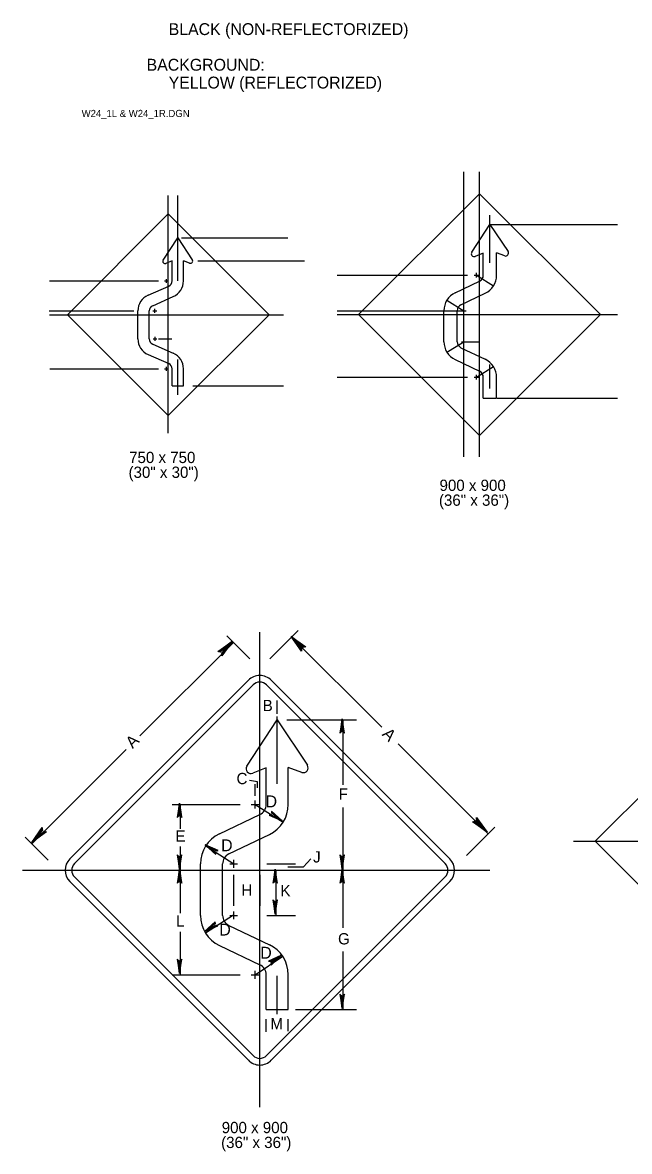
# Model space of a CAD drawing. Extents: x 0 to 0.249, y -0.213 to 0.259.
# Drawn here: x 0.0001 to 0.1279, y -0.2135 to 0.0243 of the extents above; entities that cross this region are included whole.
import ezdxf

# ---------------------------------------------------------------- set-up
doc = ezdxf.new("R2010")
doc.units = 0
doc.layers.add('1', color=7, linetype='Continuous')
doc.layers.add('3', color=7, linetype='Continuous')

# ---------------------------------------------------------------- blocks, each defined once
blk = doc.blocks.new('RARROW')
at = {"layer": '3'}
for p, q in [((-2.156, 0.28500000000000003), (-2.2665, 0.384625)), ((-2.2665, 0.384625), (0, 0)), ((0, 0), (-2.2665, -0.379125)), ((-2.156, 0.28500000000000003), (-2.075625, 0.12075)), ((0, 0), (-2.156, 0.28500000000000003)), ((-2.14975, -0.2705), (0, 0)), ((-2.075625, 0.12075), (0, 0)), ((0, 0), (-2.074, -0.108)), ((-2.2665, -0.379125), (-2.14975, -0.2705)), ((-2.074, -0.108), (-2.14975, -0.2705))]:
    blk.add_line(p, q, dxfattribs=at)

msp = doc.modelspace()

# ---------------------------------------------------------------- linework, layer by layer
at = {"layer": '1'}
for p, q in [((0.09465737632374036, -0.02410788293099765), (0.0984895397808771, -0.018239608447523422)), ((0.0984895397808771, -0.018239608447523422), (0.1253779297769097, -0.018239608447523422)), ((0.0984895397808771, -0.018239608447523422), (0.10229869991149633, -0.023980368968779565)), ((0.029677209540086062, -0.02575401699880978), (0.03274550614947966, -0.02105546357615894)), ((0.03274550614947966, -0.02105546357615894), (0.03580954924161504, -0.025673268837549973)), ((0.03354259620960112, -0.02104652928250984), (0.05594957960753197, -0.02104652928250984)), ((0.03154550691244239, -0.02592546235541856), (0.030263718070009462, -0.026459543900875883)), ((0.03154550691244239, -0.030158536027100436), (0.03154550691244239, -0.02592546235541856)), ((0.03394550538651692, -0.030158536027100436), (0.03394550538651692, -0.02592546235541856)), ((0.03524814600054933, -0.02639069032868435), (0.03394550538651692, -0.02592546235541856)), ((0.03699486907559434, -0.02591499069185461), (0.059401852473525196, -0.02591499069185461)), ((0.09708954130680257, -0.024281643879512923), (0.09539071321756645, -0.024989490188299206)), ((0.09708954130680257, -0.028938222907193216), (0.09708954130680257, -0.024281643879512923)), ((0.09988953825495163, -0.028938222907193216), (0.09988953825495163, -0.024264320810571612)), ((0.10159433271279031, -0.02487317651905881), (0.09988953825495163, -0.024264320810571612)), ((0.09568641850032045, -0.02943960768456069), (0.09568641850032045, -0.028439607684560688)), ((0.005764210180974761, -0.030154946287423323), (0.028662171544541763, -0.030154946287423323)), ((0.029926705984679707, -0.030160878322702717), (0.03076003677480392, -0.030160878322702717)), ((0.030343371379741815, -0.03057754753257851), (0.030343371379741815, -0.029744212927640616)), ((0.06631197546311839, -0.02893960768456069), (0.09378954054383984, -0.02893960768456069)), ((0.09117587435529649, -0.032651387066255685), (0.09629409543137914, -0.03020096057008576)), ((0.09518641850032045, -0.02893960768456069), (0.09618641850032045, -0.02893960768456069)), ((0.09568641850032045, -0.02893960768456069), (0.09924322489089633, -0.031176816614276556)), ((0.02649533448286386, -0.033161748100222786), (0.030828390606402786, -0.031257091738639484)), ((0.09238498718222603, -0.03517686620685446), (0.09750320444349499, -0.032726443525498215)), ((0.027461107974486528, -0.0353588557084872), (0.03179416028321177, -0.0334541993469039)), ((0.08943585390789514, -0.03420101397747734), (0.0929895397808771, -0.036439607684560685)), ((0.0056722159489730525, -0.036453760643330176), (0.02349550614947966, -0.036453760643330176)), ((0.024343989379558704, -0.04235453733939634), (0.024343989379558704, -0.036457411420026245)), ((0.026743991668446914, -0.04235453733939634), (0.026743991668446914, -0.036457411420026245)), ((0.02752732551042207, -0.036457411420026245), (0.028360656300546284, -0.036457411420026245)), ((0.02794399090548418, -0.03687407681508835), (0.02794399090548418, -0.03604074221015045)), ((0.06631197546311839, -0.036439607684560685), (0.0929895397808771, -0.036439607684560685)), ((0.08878954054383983, -0.04294057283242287), (0.08878954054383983, -0.036439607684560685)), ((0.09158954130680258, -0.04294058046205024), (0.09158954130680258, -0.036439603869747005)), ((0.0924895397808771, -0.036439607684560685), (0.0934895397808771, -0.036439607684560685)), ((0.0929895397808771, -0.036939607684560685), (0.0929895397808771, -0.035939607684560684)), ((0.027532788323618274, -0.04235338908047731), (0.028366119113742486, -0.04235338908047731)), ((0.02794945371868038, -0.0427700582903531), (0.02794945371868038, -0.041936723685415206)), ((0.02871919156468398, -0.04236008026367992), (0.03146919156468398, -0.04236008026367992)), ((0.0929895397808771, -0.043439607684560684), (0.0929895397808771, -0.04243960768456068)), ((0.02746021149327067, -0.043452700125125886), (0.03179684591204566, -0.045363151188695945)), ((0.0894362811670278, -0.045179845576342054), (0.0929895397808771, -0.042939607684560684)), ((0.09238546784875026, -0.044203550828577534), (0.09750175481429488, -0.04665064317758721)), ((0.0924895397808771, -0.042939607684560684), (0.0934895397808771, -0.042939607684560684)), ((0.0929895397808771, -0.042939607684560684), (0.09628954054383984, -0.042939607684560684)), ((0.026492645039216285, -0.0456490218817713), (0.030829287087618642, -0.04755947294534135)), ((0.0911773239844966, -0.04672948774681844), (0.09629361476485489, -0.0491765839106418)), ((0.0057697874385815, -0.04865509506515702), (0.028667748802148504, -0.04865509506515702)), ((0.029929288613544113, -0.0486578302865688), (0.03076262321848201, -0.0486578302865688)), ((0.030345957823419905, -0.04907449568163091), (0.030345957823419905, -0.0482411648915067)), ((0.03154550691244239, -0.05225546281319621), (0.03154550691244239, -0.048657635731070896)), ((0.03394550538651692, -0.05225546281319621), (0.03394550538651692, -0.04865763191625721)), ((0.0956896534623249, -0.05043960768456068), (0.09924279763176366, -0.0482002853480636)), ((0.03154550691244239, -0.05225546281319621), (0.03394550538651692, -0.05225546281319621)), ((0.03588224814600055, -0.05225546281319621), (0.05498582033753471, -0.05225546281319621)), ((0.06631197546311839, -0.05043960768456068), (0.09378954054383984, -0.05043960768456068)), ((0.0951896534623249, -0.05043960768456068), (0.0961896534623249, -0.05043960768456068)), ((0.0956896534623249, -0.050939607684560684), (0.0956896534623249, -0.04993960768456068)), ((0.09708954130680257, -0.054839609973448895), (0.09708954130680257, -0.050439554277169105)), ((0.09988953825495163, -0.054839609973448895), (0.09988953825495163, -0.05043955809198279)), ((0.09708954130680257, -0.054839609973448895), (0.09988953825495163, -0.054839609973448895)), ((0.0999895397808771, -0.054839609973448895), (0.1253779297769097, -0.054839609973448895)), ((0.047300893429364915, -0.13236573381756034), (0.05368782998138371, -0.12258527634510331)), ((0.05368782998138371, -0.12258527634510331), (0.06003643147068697, -0.13215321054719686)), ((0.05135450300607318, -0.13265533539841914), (0.048523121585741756, -0.13383507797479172)), ((0.05135450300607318, -0.1404162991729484), (0.05135450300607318, -0.13265533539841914)), ((0.05602116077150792, -0.1404162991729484), (0.05602116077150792, -0.13262646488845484)), ((0.05886248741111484, -0.13364122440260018), (0.05602116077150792, -0.13262646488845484)), ((0.04901596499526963, -0.14125194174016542), (0.04901596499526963, -0.1395852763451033)), ((0.04149839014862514, -0.14660490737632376), (0.050028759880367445, -0.14252086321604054)), ((0.048182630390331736, -0.14041860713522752), (0.04984929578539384, -0.14041860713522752)), ((0.043513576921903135, -0.15081403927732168), (0.05204393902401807, -0.14673000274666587)), ((0.044521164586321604, -0.15375194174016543), (0.044521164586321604, -0.1520852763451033)), ((0.03752116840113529, -0.16375355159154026), (0.03752116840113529, -0.1529186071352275)), ((0.042187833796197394, -0.16375356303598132), (0.042187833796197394, -0.15291860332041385)), ((0.043687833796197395, -0.1529186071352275), (0.0453544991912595, -0.1529186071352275)), ((0.043687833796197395, -0.1637519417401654), (0.0453544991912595, -0.1637519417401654)), ((0.044521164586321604, -0.1645852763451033), (0.044521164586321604, -0.16291860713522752)), ((0.043514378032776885, -0.1658585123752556), (0.05204152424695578, -0.16993700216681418)), ((0.04150080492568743, -0.17006840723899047), (0.0500279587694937, -0.17414690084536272)), ((0.04902135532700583, -0.1770852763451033), (0.04902135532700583, -0.17541860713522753)), ((0.04818802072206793, -0.17625194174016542), (0.049854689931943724, -0.17625194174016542)), ((0.05135450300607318, -0.18358528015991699), (0.05135450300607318, -0.17625185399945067)), ((0.05602116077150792, -0.18358528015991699), (0.05602116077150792, -0.17625185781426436)), ((0.05135450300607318, -0.18358528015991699), (0.05602116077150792, -0.18358528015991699))]:
    msp.add_line(p, q, dxfattribs=at)
for centre, radius, start, end in [((0.09515994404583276, -0.02443564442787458), 0.0005999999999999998, 146.8886580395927, 292.619864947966), ((0.10179613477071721, -0.02430813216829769), 0.0006, 250.34617594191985, 33.111341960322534), ((0.030345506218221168, -0.030158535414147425), 0.0012, 293.7285668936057, 0), ((0.0303455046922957, -0.03015853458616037), 0.0036000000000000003, 293.7285832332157, 5.684341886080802e-14), ((0.09568954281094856, -0.028938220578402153), 0.0014, 295.58345846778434, 0), ((0.09568953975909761, -0.028938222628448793), 0.004200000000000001, 295.5834507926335, 0), ((0.02794398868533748, -0.036457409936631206), 0.0036000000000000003, 113.72857081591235, 180), ((0.09298954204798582, -0.03643960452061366), 0.004200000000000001, 115.58345385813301, 180), ((0.02794399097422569, -0.03645740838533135), 0.0012, 113.7285780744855, 180), ((0.09298954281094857, -0.03643960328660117), 0.0014, 115.58343656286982, 180), ((0.02794398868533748, -0.04235453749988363), 0.0036000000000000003, 180, 246.22470832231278), ((0.02794399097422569, -0.04235453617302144), 0.0012, 180.00000000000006, 246.22471231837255), ((0.09298954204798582, -0.042940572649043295), 0.004200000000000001, 180.00000000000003, 244.43845176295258), ((0.09298954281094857, -0.04294057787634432), 0.0014, 180, 244.43846100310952), ((0.0303455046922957, -0.048657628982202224), 0.0036000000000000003, 0, 66.22472411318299), ((0.09568953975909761, -0.05043955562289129), 0.004200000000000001, 0, 64.4384641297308), ((0.030345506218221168, -0.048657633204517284), 0.0012, 1.4210854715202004e-14, 66.22469809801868), ((0.09568954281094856, -0.05043955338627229), 0.0014, 0, 64.43844982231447), ((0.04813850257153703, -0.13291200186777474), 0.0009999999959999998, 146.8886580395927, 292.619864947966), ((0.05919882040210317, -0.13269948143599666), 0.0009999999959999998, 250.34617594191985, 33.111341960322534), ((0.04902116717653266, -0.14041629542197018), 0.002333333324, 295.58345846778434, 0), ((0.04902116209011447, -0.14041629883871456), 0.006999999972, 295.5834507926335, 0), ((0.04452116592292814, -0.15291860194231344), 0.006999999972, 115.58345385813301, 180), ((0.044521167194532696, -0.15291859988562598), 0.002333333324, 115.58343656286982, 180), ((0.04452116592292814, -0.16375354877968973), 0.006999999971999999, 180.00000000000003, 244.43845176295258), ((0.044521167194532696, -0.16375355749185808), 0.0023333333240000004, 180, 244.43846100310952), ((0.04902116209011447, -0.17625185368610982), 0.006999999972, 0, 64.4384641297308), ((0.04902116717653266, -0.17625184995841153), 0.002333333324, 0, 64.43844982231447)]:
    msp.add_arc(centre, radius, start, end, dxfattribs=at)
at = {"layer": '3'}
for p, q in [((0.0929895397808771, -0.06719206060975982), (0.0929895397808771, -0.0071400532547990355)), ((0.09628954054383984, -0.06719206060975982), (0.09628954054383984, -0.0071400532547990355)), ((0.07083369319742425, -0.03723960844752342), (0.09628954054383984, -0.011783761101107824)), ((0.12174538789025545, -0.03723960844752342), (0.09628954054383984, -0.011783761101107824)), ((0.03074550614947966, -0.062215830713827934), (0.03074550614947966, -0.01217250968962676)), ((0.03274550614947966, -0.03015546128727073), (0.03274550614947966, -0.01217250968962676)), ((0.009532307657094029, -0.0372554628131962), (0.03074550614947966, -0.01604226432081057)), ((0.05195870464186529, -0.0372554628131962), (0.03074550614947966, -0.01604226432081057)), ((0.0984895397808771, -0.026316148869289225), (0.0984895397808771, -0.016316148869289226)), ((0.005764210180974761, -0.0372554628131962), (0.05498582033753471, -0.0372554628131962)), ((0.03074550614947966, -0.058468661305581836), (0.009532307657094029, -0.0372554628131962)), ((0.03074550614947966, -0.058468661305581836), (0.05195870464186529, -0.0372554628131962)), ((0.06631197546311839, -0.03723960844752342), (0.1253779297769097, -0.03723960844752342)), ((0.09628954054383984, -0.06269545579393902), (0.07083369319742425, -0.03723960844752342)), ((0.09628954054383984, -0.06269545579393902), (0.12174538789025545, -0.03723960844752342)), ((0.03274550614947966, -0.05416013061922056), (0.03274550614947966, -0.04667992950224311)), ((0.0984895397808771, -0.052836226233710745), (0.0984895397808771, -0.0477796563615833)), ((0.05002116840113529, -0.2041726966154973), (0.05002116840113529, -0.1040860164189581)), ((0.052142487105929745, -0.10970421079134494), (0.0581169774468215, -0.1037297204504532)), ((0.024759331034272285, -0.12597806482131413), (0.04446651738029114, -0.10627087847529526)), ((0.047899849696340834, -0.10970421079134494), (0.04305230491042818, -0.1048566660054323)), ((0.07570204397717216, -0.12414321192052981), (0.05670276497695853, -0.10514393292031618)), ((0.009998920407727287, -0.15184777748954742), (0.04761700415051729, -0.11422969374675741)), ((0.010988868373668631, -0.15283772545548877), (0.04860695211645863, -0.11521964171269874)), ((0.05143538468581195, -0.11521964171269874), (0.08905346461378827, -0.15283772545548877)), ((0.05242533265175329, -0.11422969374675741), (0.0900434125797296, -0.15184777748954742)), ((0.05368782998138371, -0.12131447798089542), (0.05368782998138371, -0.11852706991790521)), ((0.05368782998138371, -0.13604617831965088), (0.05368782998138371, -0.12187789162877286)), ((0.05568782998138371, -0.12258527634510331), (0.07040427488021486, -0.12258527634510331)), ((0.06760427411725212, -0.13627281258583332), (0.06760427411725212, -0.12258527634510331)), ((0.12062693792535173, -0.1481597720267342), (0.14608278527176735, -0.12270392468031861)), ((0.09813922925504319, -0.14658039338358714), (0.07918378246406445, -0.12762494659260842)), ((0.002040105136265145, -0.14869729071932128), (0.021883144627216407, -0.12885425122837)), ((0.04901596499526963, -0.1385852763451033), (0.04901596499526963, -0.1361297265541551)), ((0.050021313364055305, -0.1385852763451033), (0.050021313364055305, -0.1361297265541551)), ((0.031574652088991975, -0.14041860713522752), (0.0458544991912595, -0.14041860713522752)), ((0.033337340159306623, -0.14552281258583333), (0.033337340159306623, -0.14041860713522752)), ((0.04901596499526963, -0.14041860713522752), (0.05494397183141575, -0.14414728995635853)), ((0.06760427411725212, -0.15425194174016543), (0.06760427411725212, -0.1410127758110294)), ((0.005473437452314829, -0.15213062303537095), (0.0006258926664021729, -0.1472830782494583)), ((0.09357895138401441, -0.15114067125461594), (0.09955344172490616, -0.14516618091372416)), ((0.033337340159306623, -0.15425194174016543), (0.033337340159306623, -0.14927281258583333)), ((0.03864696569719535, -0.14911153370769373), (0.044521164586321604, -0.1529186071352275)), ((0.11610522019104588, -0.1481597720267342), (0.17517117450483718, -0.1481597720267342)), ((0.14608278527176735, -0.17361561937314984), (0.12062693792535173, -0.1481597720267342)), ((5.855739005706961e-05, -0.15425194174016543), (0.09850181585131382, -0.15425194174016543)), ((0.033337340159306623, -0.16327281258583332), (0.033337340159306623, -0.15425194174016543)), ((0.05152116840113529, -0.1529186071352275), (0.057521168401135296, -0.1529186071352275)), ((0.05152116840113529, -0.15424646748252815), (0.057521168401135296, -0.15424646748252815)), ((0.05345628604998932, -0.1637519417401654), (0.05345628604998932, -0.15425194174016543)), ((0.06760427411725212, -0.16639781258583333), (0.06760427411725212, -0.15425194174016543)), ((0.04761700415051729, -0.19427418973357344), (0.009998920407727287, -0.15665610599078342)), ((0.04860695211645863, -0.19328424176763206), (0.010988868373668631, -0.15566615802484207)), ((0.044521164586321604, -0.1617519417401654), (0.044521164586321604, -0.15525194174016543)), ((0.050083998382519, -0.1617519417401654), (0.050083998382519, -0.15525194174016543)), ((0.08905346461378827, -0.15566615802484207), (0.05143538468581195, -0.19328424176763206)), ((0.0900434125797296, -0.15665610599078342), (0.05242533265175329, -0.19427418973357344)), ((0.03855387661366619, -0.16741298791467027), (0.044500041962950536, -0.1636640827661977)), ((0.05152116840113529, -0.1637519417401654), (0.057521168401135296, -0.1637519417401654)), ((0.033337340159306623, -0.17625194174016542), (0.033337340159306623, -0.16719480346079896)), ((0.04902135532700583, -0.17625194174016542), (0.05485345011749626, -0.1723808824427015)), ((0.06760427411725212, -0.18358528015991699), (0.06760427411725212, -0.17132847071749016)), ((0.031574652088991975, -0.17625194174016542), (0.0458544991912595, -0.17625194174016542)), ((0.05368782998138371, -0.18457451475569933), (0.05368782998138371, -0.1765176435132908)), ((0.05752116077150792, -0.18358528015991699), (0.07040427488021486, -0.18358528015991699)), ((0.05135450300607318, -0.18827281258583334), (0.05135450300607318, -0.185585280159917)), ((0.05602116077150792, -0.18814781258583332), (0.05602116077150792, -0.185585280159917))]:
    msp.add_line(p, q, dxfattribs=at)
for points in [[(0.04950954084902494, -0.13690055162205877), (0.04950954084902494, -0.1355994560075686), (0.04782760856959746, -0.1353299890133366)], [(0.05592821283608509, -0.15354288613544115), (0.059258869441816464, -0.15354288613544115), (0.06078917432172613, -0.1518324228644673)]]:
    msp.add_lwpolyline(points, dxfattribs=at)
for centre, radius, start, end in [((0.030079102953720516, -0.026016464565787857), 0.00048, 146.85424022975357, 292.6199636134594), ((0.03540958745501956, -0.02593865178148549), 0.00048, 250.34624416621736, 33.565410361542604), ((0.0500211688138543, -0.11663385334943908), 0.0034, 44.99999742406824, 135), ((0.0500211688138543, -0.11663385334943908), 0.002, 44.99999742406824, 135), ((0.012403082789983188, -0.15425193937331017), 0.0034, 135.00000000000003, 225.00000000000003), ((0.08763925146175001, -0.15425193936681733), 0.0034, 315.0000025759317, 44.99999726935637), ((0.012403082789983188, -0.15425193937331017), 0.002, 135.00000000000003, 225.00000000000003), ((0.08763925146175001, -0.15425193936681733), 0.002, 315.0000025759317, 44.99999726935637), ((0.05002116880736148, -0.19187002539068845), 0.0034, 225, 315.00000273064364), ((0.05002116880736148, -0.19187002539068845), 0.002, 225, 315.00000273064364)]:
    msp.add_arc(centre, radius, start, end, dxfattribs=at)

# ---------------------------------------------------------------- block references
for p, xscale, yscale, rotation in [((0.056625, -0.105), 0.0016545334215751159, 0.0016366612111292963, 135.00000000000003), ((0.04425, -0.106), 0.0016545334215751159, 0.0016366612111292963, 44.999999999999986), ((0.067375, -0.122375), 0.0013236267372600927, -0.001309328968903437, 90), ((0.033125, -0.140125), 0.0013236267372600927, -0.001309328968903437, 90), ((0.05475, -0.143875), 0.0013236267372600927, -0.0013093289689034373, -32.937747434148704), ((0.097875, -0.14625), 0.0016545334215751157, 0.001636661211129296, -45), ((0.002, -0.148375), 0.001654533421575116, 0.001636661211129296, -135), ((0.0385, -0.148875), 0.0013236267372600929, -0.001309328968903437, 146.65790015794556), ((0.033125, -0.154), 0.0013236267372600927, -0.001309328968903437, -90), ((0.067375, -0.154), 0.0013236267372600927, -0.001309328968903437, -90), ((0.033125, -0.154), 0.0013236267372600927, -0.001309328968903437, 90), ((0.05325, -0.154), 0.0013236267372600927, -0.001309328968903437, 90), ((0.067375, -0.154), 0.0013236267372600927, -0.001309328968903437, 90), ((0.05325, -0.1635), 0.0013236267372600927, -0.001309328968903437, -90), ((0.038375, -0.167125), 0.0013236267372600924, -0.001309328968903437, -147.979386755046), ((0.033125, -0.176), 0.0013236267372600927, -0.001309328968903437, -90), ((0.054625, -0.172125), 0.0013236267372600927, -0.0013093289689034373, 33.673578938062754), ((0.067375, -0.183375), 0.0013236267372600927, -0.001309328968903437, -90)]:
    msp.add_blockref('RARROW', p, dxfattribs=dict(at, xscale=xscale, yscale=yscale, rotation=rotation))

# ---------------------------------------------------------------- texts
at = {"layer": '1'}
for s, height, p in [('      BLACK (NON-REFLECTORIZED)', 0.0024997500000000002, (0.02525, 0.021625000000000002)), (' BACKGROUND:', 0.0024997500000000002, (0.02525, 0.014125)), ('      YELLOW (REFLECTORIZED)', 0.0024997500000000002, (0.02525, 0.010375)), ('W24_1L & W24_1R.DGN', 0.0015, (0.0125, 0.004375))]:
    msp.add_text(s, height=height, dxfattribs=at).set_placement(p)
at = {"layer": '3'}
for s, height, p in [('750 x 750', 0.0023752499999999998, (0.0225, -0.0685)), ('(30" x 30")', 0.0023752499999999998, (0.022375, -0.07162500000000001)), ('900 x 900', 0.0023752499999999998, (0.08787500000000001, -0.074375)), ('(36" x 36")', 0.0023752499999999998, (0.08775000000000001, -0.0775)), ('B', 0.0023752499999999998, (0.050625, -0.12075)), ('C', 0.0023752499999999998, (0.045125, -0.136125)), ('F', 0.0023752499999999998, (0.066625, -0.139375)), ('D', 0.0024997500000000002, (0.051250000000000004, -0.14100000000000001)), ('E', 0.0023752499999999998, (0.03225, -0.14825)), ('D', 0.0024997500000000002, (0.041875, -0.15025)), ('J', 0.0023752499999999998, (0.06125, -0.152625)), ('H', 0.0023752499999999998, (0.046125, -0.15962500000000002)), ('K', 0.0023752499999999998, (0.054375, -0.15975)), ('L', 0.0023752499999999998, (0.032375, -0.166125)), ('D', 0.0024997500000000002, (0.0415, -0.168)), ('G', 0.0023752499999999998, (0.0665, -0.169875)), ('D', 0.0024997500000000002, (0.050125, -0.172875)), ('M', 0.0023752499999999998, (0.05225, -0.18775)), ('900 x 900', 0.0023752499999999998, (0.042, -0.209625)), ('(36" x 36")', 0.0023752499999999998, (0.041875, -0.21275))]:
    msp.add_text(s, height=height, dxfattribs=at).set_placement(p)
for rotation, p in [(315, (0.075625, -0.12575)), (45, (0.02325, -0.12875))]:
    msp.add_text('A', height=0.0024997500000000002, rotation=rotation, dxfattribs=at).set_placement(p)

doc.saveas('drawing.dxf')
